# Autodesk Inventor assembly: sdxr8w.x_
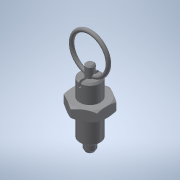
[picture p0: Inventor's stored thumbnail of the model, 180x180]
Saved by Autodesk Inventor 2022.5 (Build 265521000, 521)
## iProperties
Part Number: sdxr8w.x_
Material: 一般
Document SubType Name: Assembly
Designer: ImaoCorp
Sending System: SOLIDWORKS 2017-2017317
MC: AMD64
MC_MODEL: Intel64 Family 6 Model 60 Stepping 3, GenuineIntel
OS: Windows_NT
FRU: Parasolid Version 29.0, build 201,  4-17-2017
FORMAT: text
GUISE: transmit
KEY: sdxr8w
FILE: sdxr8w.x_t
DATE: Wed Sep 18 16:15:19 2019
Author: ImaoCorp
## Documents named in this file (3)
- X:\14_SW2022-Inv2022\00_全2023-1023新製品(TCC)まで\s\sdxr8w\SDXR8W.iam
- X:\14_SW2022-Inv2022\00_全2023-1023新製品(TCC)まで\s\sdxr8w\sdxr8w_01.ipt
- X:\14_SW2022-Inv2022\00_全2023-1023新製品(TCC)まで\s\sdxr8w\sdxr8w_02.ipt
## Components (2 placed, 2 different names)
1. sdxr8w_01
2. sdxr8w_02
